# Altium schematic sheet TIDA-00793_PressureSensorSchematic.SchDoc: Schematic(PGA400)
size 431 x 279 mm; Date: Not shown in title block; ApprovedBy: Not shown in title block; CheckedBy: Not shown in title block; Author: Not shown in title block; CompanyName: Not shown in title block; DrawnBy: Sandeep Tallada; Engineer: Not shown in title block; Organization: Not shown in title block; Address1: Not shown in title block; Address2: Not shown in title block; Address3: Not shown in title block; Address4: Not shown in title block; DocumentNumber: 1; Revision: Use project parameter SCH_Rev; SheetNumber: 2; SheetTotal: 3; PageSetup: Record=PageOptions¦CenterHorizontal=True¦CenterVertical=True¦PrintScale=1.00¦XCorrection=1.00¦YCorrection=1.00¦PrintKind=0¦BorderSize=5000000¦LeftOffset=0¦BottomOffset=0¦Orientation=2¦PaperLength=1000¦PaperWidth=1000¦Scale=100¦PaperSource=15¦PrintQuality=600¦MediaType=1¦DitherType=10¦PaperKind=Letter¦PrintScaleMode=1
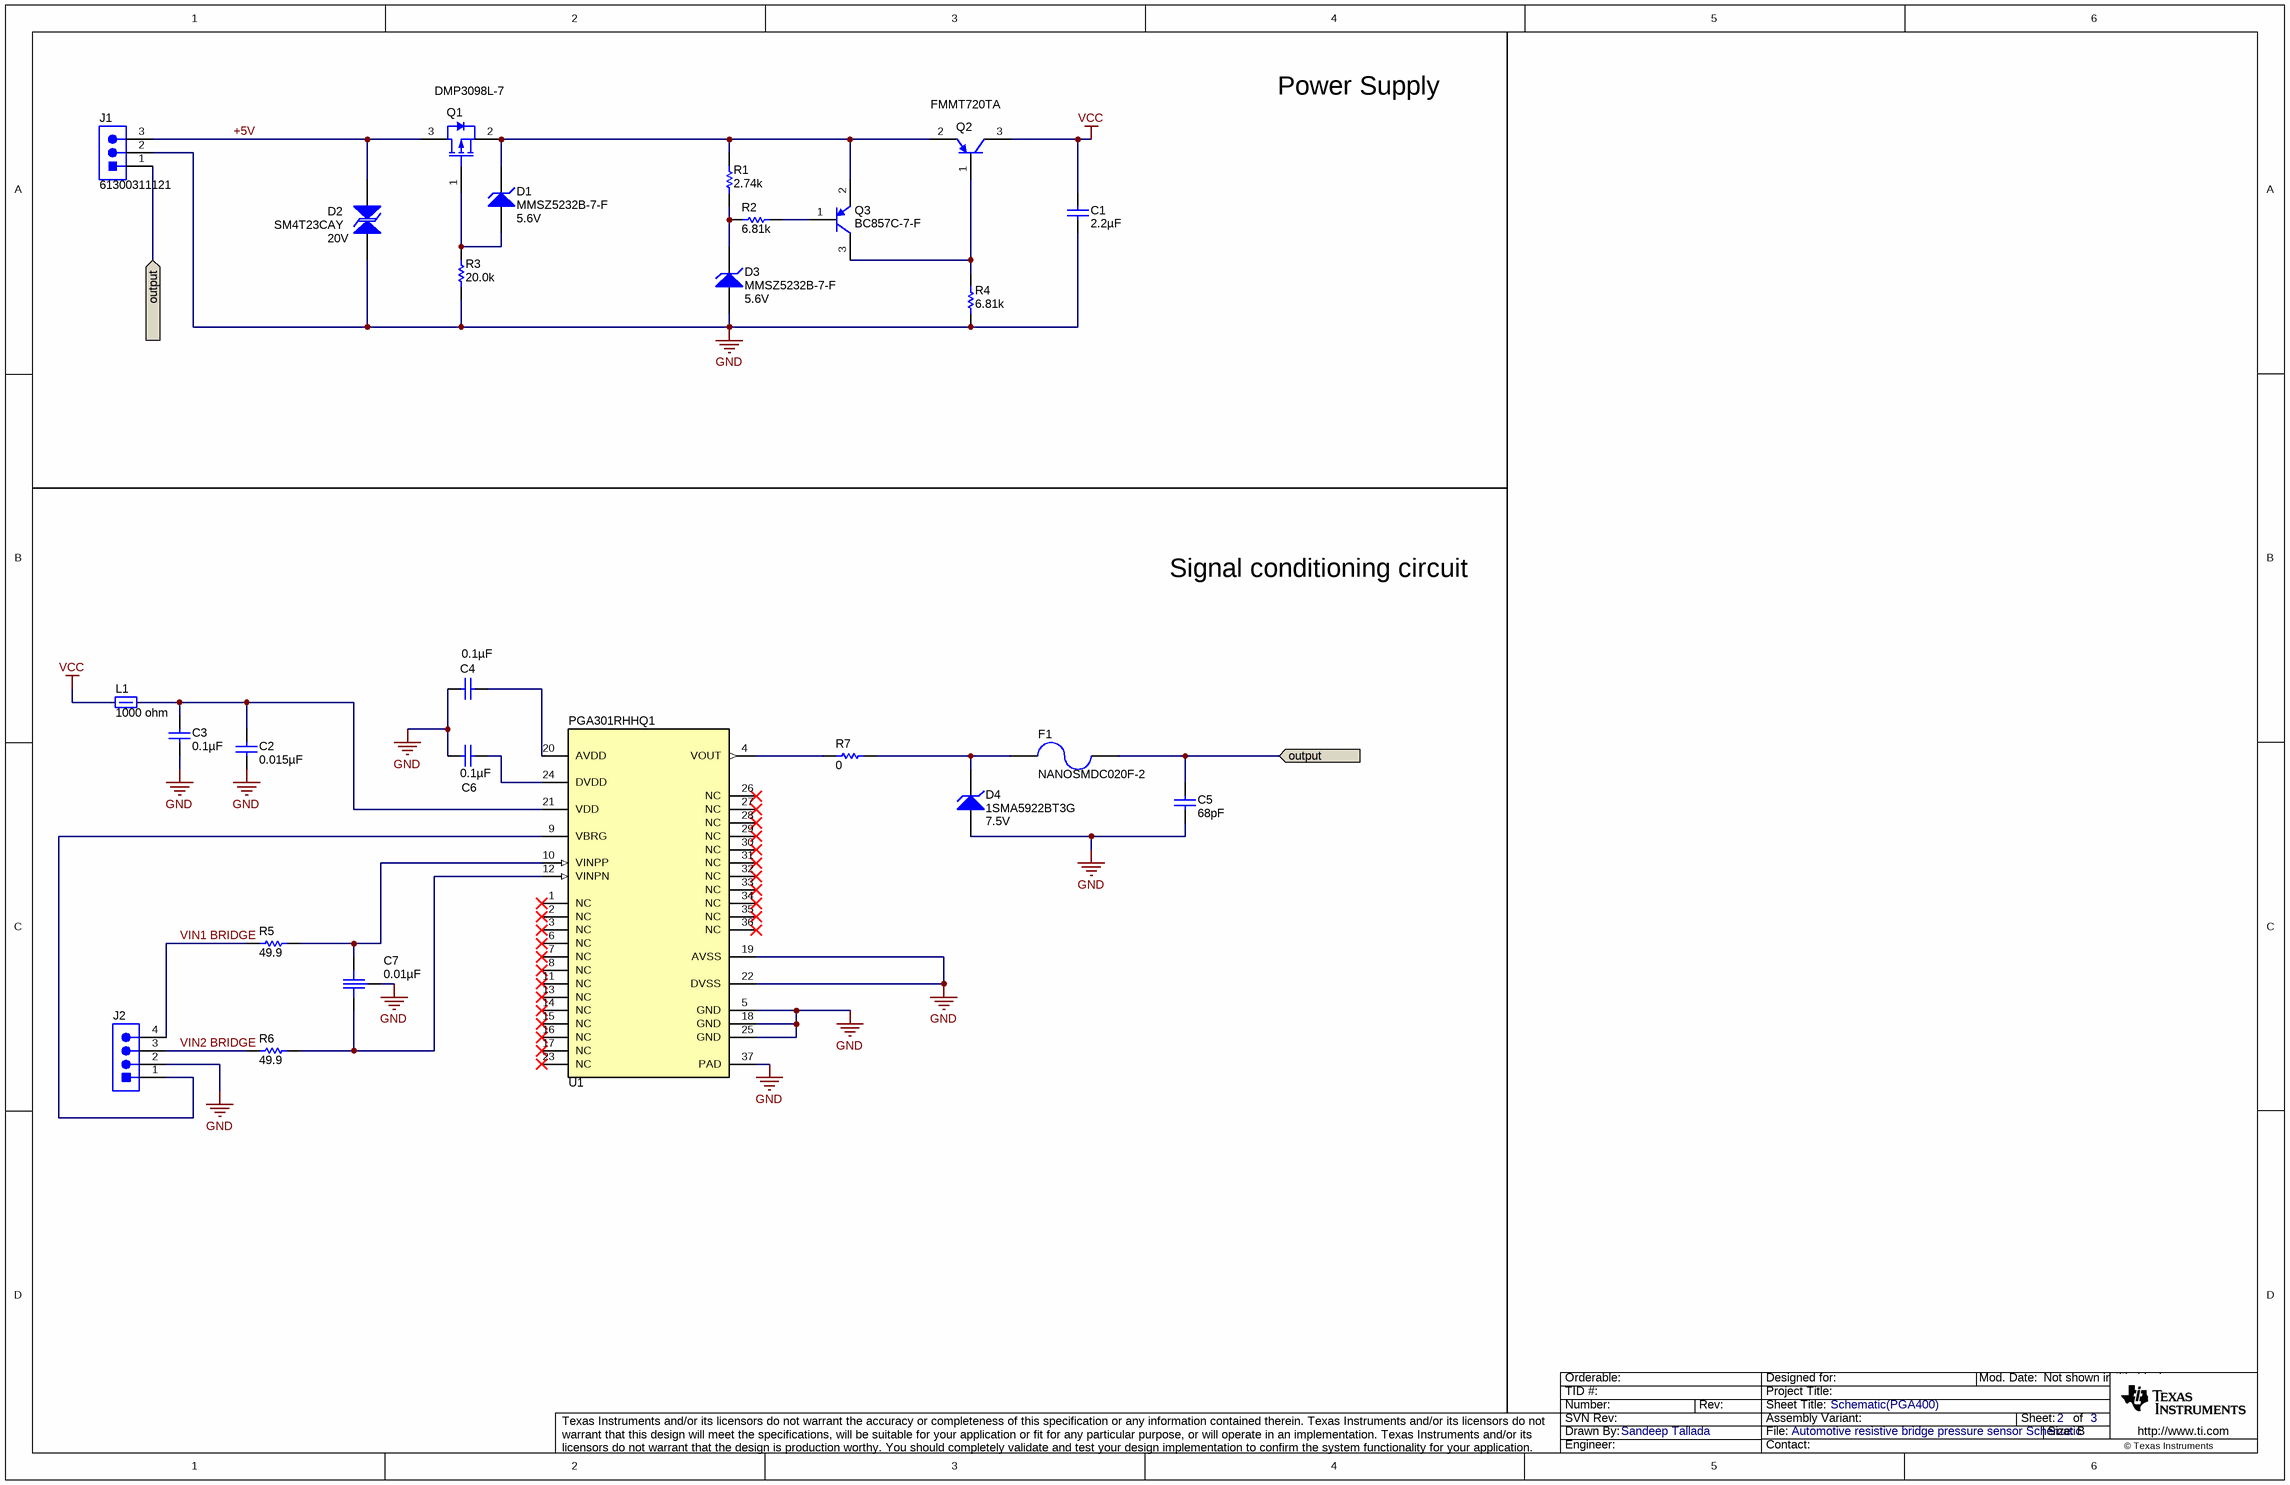
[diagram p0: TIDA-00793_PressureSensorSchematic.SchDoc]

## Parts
C1  ValueDisplayed: 2.2µF  [0603]  (hidden comment: GRM188Z71C225KE43)
C2  ValueDisplayed: 0.015µF  [0402]  (hidden comment: GRM155R71C153JA01D)
C3  ValueDisplayed: 0.1µF  [0402]  (hidden comment: GRM155R71C104JA88D)
C4  ValueDisplayed: 0.1µF  [0603S]  (hidden comment: 0603YC104JAT2A)
C5  ValueDisplayed: 68pF  [0603]  (hidden comment: C0603C680J5GACTU)
C6  ValueDisplayed: 0.1µF  [0603S]  (hidden comment: 0603YC104JAT2A)
C7  ValueDisplayed: 0.01µF  [X2Y_0603]  (hidden comment: 500X14W103MV4T)
D1  MMSZ5232B-7-F  value 5.6V  [SOD-123]
D2  SM4T23CAY  value 20V  [SMA]
D3  MMSZ5232B-7-F  value 5.6V  [SOD-123]
D4  1SMA5922BT3G  value 7.5V  [SMA]
F1  NANOSMDC020F-2  [FUSE_NANO02]
J1  61300311121  [WURTH_61300311121]
J2  61300411121  [WURTH_61300411121]  (value not drawn)
L1  value 1000 ohm  [0603]  (hidden comment: 74279266)
Q1  DMP3098L-7  [SOT-23]
Q2  FMMT720TA  [SOT-23]
Q3  BC857C-7-F  [SOT-23]
R1  ValueDisplayed: 2.74k  [0402]  (hidden comment: CRCW04022K74FKED)
R2  ValueDisplayed: 6.81k  [0402]  (hidden comment: CRCW04026K81FKED)
R3  ValueDisplayed: 20.0k  [0603]  (hidden comment: CRCW060320K0FKEA)
R4  ValueDisplayed: 6.81k  [0402]  (hidden comment: CRCW04026K81FKED)
R5  ValueDisplayed: 49.9  [0402]  (hidden comment: CRCW040249R9FKED)
R6  ValueDisplayed: 49.9  [0402]  (hidden comment: CRCW040249R9FKED)
R7  ValueDisplayed: 0  [0603S]  (hidden comment: MCR03EZPJ000)
U1  PGA301RHHQ1  [RHH0036C_NV]

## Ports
output

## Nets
GND: C1.2 C2.2 C3.2 C4.1 C5.2 C6.1 C7.3 D2.1 D3.2(A) D4.2(A) J1.2 J2.2 R3.1 R4.1 U1.5(GND) U1.18(GND) U1.19(AVSS) U1.22(DVSS) U1.25(GND) U1.37(PAD)
VCC: C1.1 L1.1 Q2.3(C)
+5V: D2.2 J1.3 Q1.3(D)
output: C5.1 F1.1 J1.1 ; port output
VIN1 BRIDGE: J2.4 R5.1
VIN2 BRIDGE: J2.3 R6.1
NetC2_1: C2.1 C3.1 L1.2 U1.21(VDD)
NetC4_2: C4.2 U1.20(AVDD)
NetC6_2: C6.2 U1.24(DVDD)
NetC7_1: C7.1 R6.2 U1.12(VINPN)
NetC7_2: C7.2 R5.2 U1.10(VINPP)
NetD1_1: D1.1(K) Q1.2(S) Q2.2(E) Q3.2(E) R1.2
NetD1_2: D1.2(A) Q1.1(G) R3.2
NetD3_1: D3.1(K) R1.1 R2.1
NetD4_1: D4.1(K) F1.2 R7.2
NetJ2_1: J2.1 U1.9(VBRG)
NetQ2_1: Q2.1(B) Q3.3(C) R4.2
NetQ3_1: Q3.1(B) R2.2
NetR7_1: R7.1 U1.4(VOUT)

Not connected (* = marked no-connect by the designer): U1 1(NC)* 2(NC)* 3(NC)* 6(NC)* 7(NC)* 8(NC)* 11(NC)* 13(NC)* 14(NC)* 15(NC)* 16(NC)* 17(NC)* 23(NC)* 26(NC)* 27(NC)* 28(NC)* 29(NC)* 30(NC)* 31(NC)* 32(NC)* 33(NC)* 34(NC)* 35(NC)* 36(NC)*

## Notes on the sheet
- Power Supply
- Signal conditioning circuit

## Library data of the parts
C1 = GRM188Z71C225KE43: CAP, CERM, 2.2 µF, 16 V, +/- 10%, X7R, 0603; Manufacturer: MuRata; Polarized: N; CompType: Capacitor; Value: 2.2uF; U/M: EA; Cap_F: 0.0000022; Tolerance_%: 10; Value1: Unknown; VDC_V: 16; Value2: 16V; TaMin_C: -55; TaMax_C: 125; AEC Category: Q200
C2 = GRM155R71C153JA01D: CAP, CERM, 0.015 µF, 16 V, +/- 5%, X7R, 0402; Manufacturer: MuRata; Polarized: N; CompType: Capacitor; Value: 0.015uF; U/M: EA; Cap_F: 0.000000015; Tolerance_%: 5; Value1: Unknown; VDC_V: 16; Value2: 16V; TaMin_C: -55; TaMax_C: 125; AEC Category: Q200
C3 = GRM155R71C104JA88D: CAP, CERM, 0.1 µF, 16 V, +/- 5%, X7R, 0402; Manufacturer: MuRata; Polarized: N; CompType: Capacitor; Value: 0.1uF; U/M: EA; Cap_F: 0.0000001; Tolerance_%: 5; Value1: Unknown; VDC_V: 16; Value2: 16V; TaMin_C: -55; TaMax_C: 125; AEC Category: Q200
C4 C6 = 0603YC104JAT2A: CAP, CERM, 0.1 µF, 16 V, +/- 5%, X7R, 0603; Manufacturer: AVX; Polarized: N; CompType: Capacitor; Value: 0.1uF; U/M: EA; Cap_F: 0.0000001; Tolerance_%: 5; ESR_ohm: 0.039; Value1: 0.039 ohm; VDC_V: 16; Value2: 16V; TaMin_C: -55; TaMax_C: 125; Cap_Case: 0603; AEC Category: Q200
C5 = C0603C680J5GACTU: CAP, CERM, 68 pF, 50 V, +/- 5%, C0G/NP0, 0603; Manufacturer: Kemet; Polarized: N; CompType: Capacitor; Value: 68pF; U/M: EA; Cap_F: 0.000000000068; Tolerance_%: 5; Value1: Unknown; VDC_V: 50; Value2: 50V; TaMin_C: -55; TaMax_C: 125; AEC Category: Q200
C7 = 500X14W103MV4T: CAP, CERM, 0.01 µF, 50 V, +/- 20%, X7R, 0603; Manufacturer: Johanson Technology; SymbolCreator: a0411947; CompType: Capacitor; U/M: EA; Cap_F: 0.00000001; Value: 0.01uF; Tolerance_%: 20; Value1: Unknown; VDC_V: 50; Value2: 50V; TaMin_C: -55; TaMax_C: 125; Polarized: N; Cap_Case: 0603; AEC Category: Q200
D1 D3 = MMSZ5232B-7-F: Diode, Zener, 5.6 V, 500 mW, SOD-123; Manufacturer: Diodes Inc.; SymbolCreator: a0412235; U/M: EA; Power_W: 0.5; Vz_V: 5.6; Value1: 0.5W; RJA_CperW: 350; AEC Category: Q101
D2 = SM4T23AY/CAY: Diode, TVS, Bi, 20 V, 400 W, AEC-Q101, SMA; Manufacturer: STMicroelectronics; U/M: EA; Power_W: 400; Vr_V: 20; Value1: 400W; AEC Category: Q101; AEC Qualified: Y
D4 = 1SMA5922BT3G: Diode, Zener, 7.5 V, 1.5 W, AEC-Q101, SMA; Manufacturer: ON Semiconductor; SymbolCreator: a0412235; U/M: EA; Power_W: 1.5; Vz_V: 7.5; Value1: 1.5W; RJA_CperW: 250; AEC Category: Q101; AEC Qualified: Y
F1 = NANOSMDC020F-2: Fuse, Resettable, 0.2 A, 24 V, SMD; Manufacturer: TE Connectivity; SymbolCreator: a0412235; U/M: EA; OpeningTime_100%_min: 0.1; VDC_V: 24; Irating_A: 0.2; Rtyp_Ohm: 1.875
J1 = 61300311121: Header, 2.54 mm, 3x1, Gold, TH; Manufacturer: Wurth Elektronik; SymbolCreator: a0799628; U/M: EA
J2 = 61300411121: Header, 2.54 mm, 4x1, Gold, TH; Manufacturer: Wurth Elektronik; SymbolCreator: a0412235; U/M: EA
L1 = 74279266: Ferrite Bead, 1000 ohm @ 100 MHz, 0.2 A, 0603; Manufacturer: Wurth Elektronik; Imax_A: 0.2; DCR_ohm: 0.6; Value1: 0.6 ohm; Value2: 0.2A; ZTyp@100MHz_Ohm: 1000
Q1 = DMP3098L-7: MOSFET, P-CH, -30 V, -3.8 A, AEC-Q101, SOT-23; Manufacturer: Diodes Inc.; Alternate Manufacturer: None; U/M: EA; ChType: P; Value: -30V; Value1: 0.12 ohm; Rdson45_ohm: 0.12; Value2: 4 nC; QgTyp_nC: 4; Vgs_V: 20; AEC Category: Q101; AEC Qualified: Y
Q2 = FMMT720TA, Diodes Inc.: Transistor, PNP, 40 V, 1.5 A, AEC-Q101, SOT-23; CompType: BJT; PNP: 1; NPN: 0; Vceo_V: 40; Vcesat1_V: 26; Value: 40 V; IcRated_A: 1.5; Value1: 1.5 A; TaMin_C: -55; TaMax_C: 150; U/M: EA; AEC Category: Q101; AEC Qualified: Y
Q3 = BC857C-7-F, Diodes Inc.: Transistor, PNP, 45 V, 0.1 A, SOT-23; CompType: BJT; PNP: 1; NPN: 0; Vceo_V: 45; Vcesat1_V: 0.075; Value: 45 V; IcRated_A: 0.1; Value1: 0.1 A; HfeMax: 600; TaMin_C: -65; TaMax_C: 150; U/M: EA; AEC Category: Q101
R1 = CRCW04022K74FKED: RES, 2.74 k, 1%, 0.063 W, 0402; Manufacturer: Vishay-Dale; CompType: Resistor; Value: 2.74k; Res_ohm: 2740; Value_Code: 2k74; Tolerance_%: 1; Power_W: 0.063; Value2: 0.063W; VDC_V: 50; TempCo: 100 ppm/C; EIA_Code: E96; U/M: EA; AEC Category: Q200
R2 R4 = CRCW04026K81FKED: RES, 6.81 k, 1%, 0.063 W, 0402; Manufacturer: Vishay-Dale; CompType: Resistor; Value: 6.81k; Res_ohm: 6810; Value_Code: 6k81; Tolerance_%: 1; Power_W: 0.063; Value2: 0.063W; VDC_V: 50; TempCo: 100 ppm/C; EIA_Code: E96; U/M: EA; AEC Category: Q200
R3 = CRCW060320K0FKEA: RES, 20.0 k, 1%, 0.1 W, 0603; Manufacturer: Vishay-Dale; CompType: Resistor; Value: 20.0k; Res_ohm: 20000; Value_Code: 20k0; Tolerance_%: 1; Power_W: 0.1; Value2: 0.1W; VDC_V: 75; TempCo: 100 ppm/C; EIA_Code: E96; U/M: EA; AEC Category: Q200
R5 R6 = CRCW040249R9FKED: RES, 49.9, 1%, 0.063 W, 0402; Manufacturer: Vishay-Dale; CompType: Resistor; Value: 49.9; Value_Code: 49R9; Tolerance_%: 1; Power_W: 0.063; Value2: 0.063W; VDC_V: 50; TempCo: 100 ppm/C; EIA_Code: E96; U/M: EA; AEC Category: Q200
R7 = MCR03EZPJ000: RES, 0, 5%, 0.1 W, 0603; Manufacturer: Rohm; CompType: Resistor; Value: 0; Value_Code: 0000; Tolerance_%: 5; Power_W: 0.1; Value2: 0.1W; TempCo: ppm/C; EIA_Code: E24; U/M: EA; AEC Category: Q200; AEC Qualified: N
U1 = PGA301RHHQ1: Resistive Bridge Sensor Signal Conditioner for Automotive application, RHH0036C; Manufacturer: Texas Instruments; SymbolCreator: Altium; CompType: IC; U/M: EA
